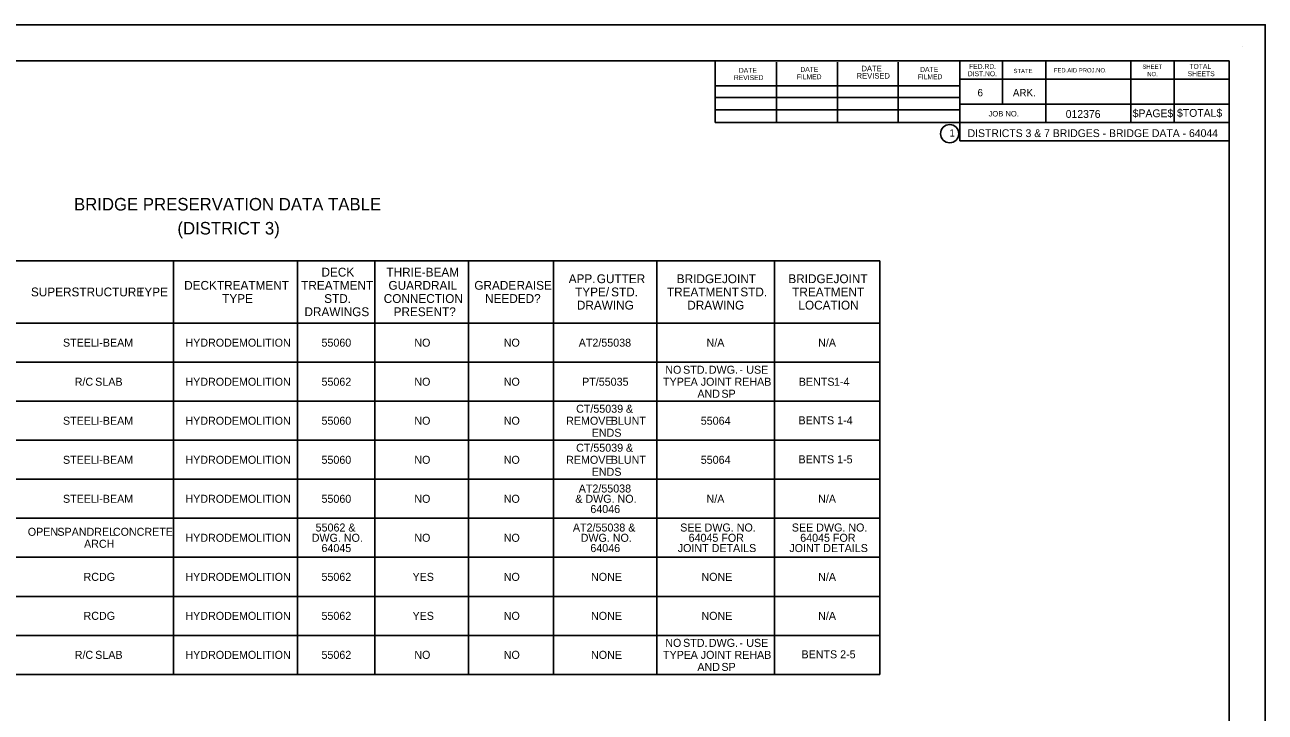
# Model space of a CAD drawing. Extents: x 16 to 1228740, y 11 to 152440.
# Drawn here: x 16.836 to 18.49, y 11.626 to 12.543 of the extents above; entities that cross this region are included whole.
import ezdxf

# ---------------------------------------------------------------- set-up
doc = ezdxf.new("R2010")
doc.units = 0
for name, color, linetype in [('B_Copy In', 7, 'Continuous'), ('B_Text', 7, 'Continuous'), ('R_Border', 7, 'Continuous')]:
    doc.layers.add(name, color=color, linetype=linetype)

msp = doc.modelspace()

# ---------------------------------------------------------------- linework, layer by layer
at = {"layer": 'B_Text'}
for p, q in [((16.2489, 12.2282), (17.9766, 12.2282)), ((17.0347, 11.6766), (17.0347, 12.2282)), ((17.2002, 11.6766), (17.2002, 12.2282)), ((17.3032, 11.6766), (17.3032, 12.2282)), ((17.4281, 11.6766), (17.4281, 12.2282)), ((17.5415, 11.6766), (17.5415, 12.2282)), ((17.6789, 11.6766), (17.6789, 12.2282)), ((17.8361, 11.6766), (17.8361, 12.2282)), ((17.9766, 11.6766), (17.9766, 12.2282)), ((16.2489, 12.1449), (17.9766, 12.1449)), ((16.2489, 12.0929), (17.9766, 12.0929)), ((16.2489, 12.0408), (17.9766, 12.0408)), ((16.2489, 11.9888), (17.9766, 11.9888)), ((16.2489, 11.9368), (17.9766, 11.9368)), ((16.2489, 11.8847), (17.9766, 11.8847)), ((16.2489, 11.8327), (17.9766, 11.8327)), ((16.2489, 11.7806), (17.9766, 11.7806)), ((16.2489, 11.7286), (17.9766, 11.7286)), ((16.2489, 11.6766), (17.9766, 11.6766))]:
    msp.add_line(p, q, dxfattribs=at)
at = {"layer": 'R_Border'}
for p, q in [((18.4604, 12.514), (18.4604, 12.514)), ((15.7833, 12.4948), (18.4422, 12.4948)), ((17.7567, 12.4124), (17.7567, 12.4948)), ((17.8389, 12.4124), (17.8389, 12.4931)), ((17.9202, 12.4124), (17.9202, 12.4931)), ((18.0009, 12.4124), (18.0009, 12.4931)), ((18.083, 12.4948), (18.083, 12.3881)), ((18.14, 12.4948), (18.14, 12.4369)), ((18.1979, 12.4948), (18.1979, 12.4124)), ((18.311, 12.4948), (18.311, 12.4124)), ((18.3689, 12.4948), (18.3689, 12.4124)), ((18.4422, 10.7576), (18.4422, 12.4948)), ((18.4422, 12.4703), (18.083, 12.4703)), ((18.4422, 12.4704), (18.4422, 12.4704)), ((17.7567, 12.4613), (18.083, 12.4613)), ((17.7567, 12.4458), (18.083, 12.4458)), ((17.7567, 12.4124), (17.7567, 12.4296)), ((17.7567, 12.4296), (18.083, 12.4296)), ((18.4422, 12.4369), (18.083, 12.4369)), ((18.1077, 12.4369), (18.4422, 12.4369)), ((18.4422, 12.4124), (17.7567, 12.4124)), ((18.083, 12.3881), (18.4422, 12.3881)), ((18.083, 12.3881), (18.4422, 12.3881))]:
    msp.add_line(p, q, dxfattribs=at)
msp.add_lwpolyline([(15.6569, 12.5428), (18.4903, 12.5428), (18.4903, 10.7095), (15.6569, 10.7095)], close=True, dxfattribs=at)
msp.add_circle((18.0696, 12.3976), 0.0122, dxfattribs=at)

# ---------------------------------------------------------------- texts
at = {"layer": 'B_Copy In'}
msp.add_text('DISTRICTS 3 & 7 BRIDGES - BRIDGE DATA - 64044', height=0.0104, dxfattribs=at).set_placement((18.0935, 12.3931))
at = {"layer": 'B_Text'}
for s, p in [('BRIDGE PRESERVATION DATA TABLE ', (16.902, 12.2952)), ('(DISTRICT 3)', (17.0399, 12.2632))]:
    msp.add_text(s, height=0.0167, rotation=360, dxfattribs=at).set_placement(p)
for s, height, p in [('DECK', 0.01174, (17.232, 12.2071)), ('THRIE-BEAM', 0.01174, (17.3186, 12.2071)), ('APP.', 0.01174, (17.5616, 12.1983)), (' GUTTER', 0.01174, (17.5947, 12.1983)), ('BRIDGE', 0.01174, (17.7057, 12.1983)), (' JOINT', 0.01174, (17.7616, 12.1983)), ('BRIDGE', 0.01174, (17.8545, 12.1983)), (' JOINT', 0.01174, (17.9104, 12.1983)), ('SUPERSTRUCTURE', 0.011742, (16.8446, 12.1807)), (' TYPE', 0.01174, (16.9819, 12.1807)), ('DECK', 0.01174, (17.0489, 12.1895)), (' TREATMENT', 0.01174, (17.0883, 12.1895)), ('TREATMENT', 0.01174, (17.2049, 12.1895)), ('GUARDRAIL', 0.01174, (17.3213, 12.1895)), ('GRADE', 0.01174, (17.4358, 12.1895)), (' RAISE', 0.01174, (17.4877, 12.1895)), ('TYPE/', 0.01174, (17.5702, 12.1807)), (' STD.', 0.01174, (17.6139, 12.1807)), ('TREATMENT', 0.01174, (17.6926, 12.1807)), (' STD.', 0.01174, (17.7861, 12.1807)), ('TREATMENT', 0.01174, (17.8596, 12.1807)), ('TYPE', 0.01174, (17.0996, 12.1719)), ('STD.', 0.01174, (17.2356, 12.1719)), ('CONNECTION', 0.01174, (17.315, 12.1719)), ('NEEDED?', 0.01174, (17.4501, 12.1719)), ('DRAWING', 0.01174, (17.5725, 12.1631)), ('DRAWING', 0.01174, (17.7197, 12.1631)), ('LOCATION', 0.01174, (17.8679, 12.1631)), ('DRAWINGS', 0.01174, (17.2093, 12.1543)), ('PRESENT?', 0.01174, (17.3282, 12.1543)), ('STEEL', 0.01067, (16.8873, 12.1136)), (' I-BEAM', 0.01067, (16.9278, 12.1136)), ('HYDRODEMOLITION', 0.010675, (17.0506, 12.1136)), ('55060', 0.01067, (17.232, 12.1136)), ('NO', 0.01067, (17.3558, 12.1136)), ('NO', 0.01067, (17.475, 12.1136)), ('AT2/55038', 0.01067, (17.575, 12.1136)), ('N/A', 0.01067, (17.7454, 12.1136)), ('N/A', 0.01067, (17.8942, 12.1136)), ('NO', 0.01067, (17.6904, 12.0775)), (' STD.', 0.01067, (17.7102, 12.0775)), (' DWG.', 0.01067, (17.7445, 12.0775)), (' -', 0.01067, (17.7852, 12.0775)), (' USE', 0.01067, (17.7944, 12.0775)), ('R/C', 0.01067, (16.903, 12.0615)), (' SLAB', 0.01067, (16.9263, 12.0615)), ('HYDRODEMOLITION', 0.010675, (17.0506, 12.0615)), ('55062', 0.01067, (17.232, 12.0615)), ('NO', 0.01067, (17.3558, 12.0615)), ('NO', 0.01067, (17.475, 12.0615)), ('PT/55035', 0.01067, (17.5795, 12.0615)), ('TYPE', 0.01067, (17.6874, 12.0615)), (' A', 0.01067, (17.7203, 12.0615)), (' JOINT', 0.01067, (17.7337, 12.0615)), (' REHAB', 0.01067, (17.7787, 12.0615)), ('BENTS', 0.01067, (17.8684, 12.0615)), (' 1-4', 0.01067, (17.9114, 12.0615)), ('AND', 0.01067, (17.7332, 12.0455)), (' SP', 0.01067, (17.7613, 12.0455)), ('CT/55039', 0.01067, (17.5715, 12.0255)), (' &', 0.01067, (17.634, 12.0255)), ('STEEL', 0.01067, (16.8873, 12.0095)), (' I-BEAM', 0.01067, (16.9278, 12.0095)), ('HYDRODEMOLITION', 0.010675, (17.0506, 12.0095)), ('55060', 0.01067, (17.232, 12.0095)), ('NO', 0.01067, (17.3558, 12.0095)), ('NO', 0.01067, (17.475, 12.0095)), ('REMOVE', 0.01067, (17.5582, 12.0095)), (' BLUNT', 0.01067, (17.6138, 12.0095)), ('55064', 0.01067, (17.7377, 12.0095)), ('BENTS 1-4', 0.01067, (17.868, 12.01)), ('ENDS', 0.01067, (17.5923, 11.9935)), ('CT/55039', 0.01067, (17.5715, 11.9735)), (' &', 0.01067, (17.634, 11.9735)), ('STEEL', 0.01067, (16.8873, 11.9574)), (' I-BEAM', 0.01067, (16.9278, 11.9574)), ('HYDRODEMOLITION', 0.010675, (17.0506, 11.9574)), ('55060', 0.01067, (17.232, 11.9574)), ('NO', 0.01067, (17.3558, 11.9574)), ('NO', 0.01067, (17.475, 11.9574)), ('REMOVE', 0.01067, (17.5582, 11.9574)), (' BLUNT', 0.01067, (17.6138, 11.9574)), ('55064', 0.01067, (17.7377, 11.9574)), ('BENTS 1-5', 0.01067, (17.868, 11.958)), ('ENDS', 0.01067, (17.5923, 11.9414)), ('AT2/55038', 0.01067, (17.575, 11.9191)), ('STEEL', 0.01067, (16.8873, 11.9054)), (' I-BEAM', 0.01067, (16.9278, 11.9054)), ('HYDRODEMOLITION', 0.010675, (17.0506, 11.9054)), ('55060', 0.01067, (17.232, 11.9054)), ('NO', 0.01067, (17.3558, 11.9054)), ('NO', 0.01067, (17.475, 11.9054)), ('& DWG. NO.', 0.01067, (17.5704, 11.9054)), ('N/A', 0.01067, (17.7454, 11.9054)), ('N/A', 0.01067, (17.8942, 11.9054)), ('64046', 0.01067, (17.5905, 11.8917)), ('55062 &', 0.01067, (17.2242, 11.8671)), ('AT2/55038 &', 0.010675, (17.5672, 11.8671)), ('SEE DWG. NO.', 0.010675, (17.7103, 11.8671)), ('SEE DWG. NO.', 0.010675, (17.8591, 11.8671)), ('OPEN', 0.01067, (16.8404, 11.8614)), (' SPANDREL', 0.01067, (16.8759, 11.8614)), (' CONCRETE', 0.01067, (16.9499, 11.8614)), ('HYDRODEMOLITION', 0.010675, (17.0506, 11.8534)), ('DWG. NO.', 0.01067, (17.219, 11.8534)), ('NO', 0.01067, (17.3558, 11.8534)), ('NO', 0.01067, (17.475, 11.8534)), ('DWG. NO.', 0.01067, (17.5776, 11.8534)), ('64045 FOR', 0.01067, (17.7215, 11.8534)), ('64045 FOR', 0.01067, (17.8703, 11.8534)), ('ARCH', 0.01067, (16.9154, 11.8454)), ('64045', 0.01067, (17.232, 11.8397)), ('64046', 0.01067, (17.5905, 11.8397)), ('JOINT DETAILS', 0.010675, (17.707, 11.8397)), ('JOINT DETAILS', 0.010675, (17.8558, 11.8397)), ('RCDG', 0.01067, (16.9147, 11.8013)), ('HYDRODEMOLITION', 0.010675, (17.0506, 11.8013)), ('55062', 0.01067, (17.232, 11.8013)), ('YES', 0.01067, (17.3534, 11.8013)), ('NO', 0.01067, (17.475, 11.8013)), ('NONE', 0.01067, (17.5914, 11.8013)), ('NONE', 0.01067, (17.7386, 11.8013)), ('N/A', 0.01067, (17.8942, 11.8013)), ('RCDG', 0.01067, (16.9147, 11.7493)), ('HYDRODEMOLITION', 0.010675, (17.0506, 11.7493)), ('55062', 0.01067, (17.232, 11.7493)), ('YES', 0.01067, (17.3534, 11.7493)), ('NO', 0.01067, (17.475, 11.7493)), ('NONE', 0.01067, (17.5914, 11.7493)), ('NONE', 0.01067, (17.7386, 11.7493)), ('N/A', 0.01067, (17.8942, 11.7493)), ('NO', 0.01067, (17.6904, 11.7133)), (' STD.', 0.01067, (17.7102, 11.7133)), (' DWG.', 0.01067, (17.7445, 11.7133)), (' -', 0.01067, (17.7852, 11.7133)), (' USE', 0.01067, (17.7944, 11.7133)), ('R/C', 0.01067, (16.903, 11.6973)), (' SLAB', 0.01067, (16.9263, 11.6973)), ('HYDRODEMOLITION', 0.010675, (17.0506, 11.6973)), ('55062', 0.01067, (17.232, 11.6973)), ('NO', 0.01067, (17.3558, 11.6973)), ('NO', 0.01067, (17.475, 11.6973)), ('NONE', 0.01067, (17.5914, 11.6973)), ('TYPE', 0.01067, (17.6874, 11.6973)), (' A', 0.01067, (17.7203, 11.6973)), (' JOINT', 0.01067, (17.7337, 11.6973)), (' REHAB', 0.01067, (17.7787, 11.6973)), ('BENTS 2-5', 0.01067, (17.872, 11.698)), ('AND', 0.01067, (17.7332, 11.6812)), (' SP', 0.01067, (17.7613, 11.6812))]:
    msp.add_text(s, height=height, dxfattribs=at).set_placement(p)
at = {"layer": 'R_Border'}
for s, height, p in [('DATE', 0.00733, (17.952, 12.4809)), ('FED.RD.', 0.00652, (18.0954, 12.4841)), ('SHEET', 0.0057, (18.3265, 12.4841)), ('TOTAL', 0.00652, (18.3892, 12.4841)), ('REVISED', 0.00652, (17.7818, 12.4691)), ('DATE', 0.00652, (17.7885, 12.4788)), ('FILMED', 0.00652, (17.8657, 12.4703)), ('DATE', 0.00652, (17.8705, 12.4801)), ('REVISED', 0.00733, (17.9455, 12.4711)), ('FILMED', 0.00652, (18.0269, 12.4703)), ('DATE', 0.00652, (18.0302, 12.4801)), ('DIST.NO.', 0.00652, (18.0937, 12.4743)), ('STATE', 0.0057, (18.1547, 12.4784)), ('FED.AID PROJ.NO.', 0.0057, (18.2085, 12.4793)), ('NO.', 0.0057, (18.333, 12.4743)), ('SHEETS', 0.00652, (18.3869, 12.4743)), ('6', 0.00977, (18.1067, 12.4474)), ('ARK.', 0.00977, (18.1539, 12.4474)), ('JOB NO.', 0.00733, (18.1214, 12.4206)), ('012376', 0.0104, (18.2243, 12.4187)), ('$PAGE$', 0.0104, (18.3136, 12.4196)), ('$TOTAL$', 0.0104, (18.3727, 12.4201)), ('1', 0.00977, (18.0693, 12.3937))]:
    msp.add_text(s, height=height, dxfattribs=at).set_placement(p)

doc.saveas('drawing.dxf')
